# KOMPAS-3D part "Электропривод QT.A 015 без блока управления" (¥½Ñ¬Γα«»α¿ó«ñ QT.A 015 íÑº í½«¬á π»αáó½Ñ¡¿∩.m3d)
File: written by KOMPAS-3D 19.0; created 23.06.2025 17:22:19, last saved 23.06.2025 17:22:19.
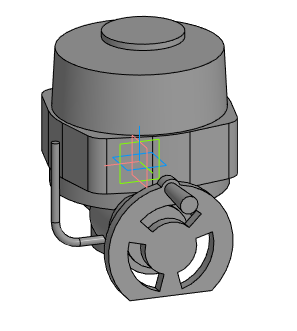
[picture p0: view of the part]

Document properties: Автор: Евгений; Полное имя файла: E:\Dendor Работа Сачек\3D для проектировщиков\3.5 Тип QT.А Электропривод\stp_Электропривод QT.A без блока управления\Электропривод QT.A 015 без блока управления.m3d

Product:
- Part/product: Электропривод QT.A 015 без блока управления

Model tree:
1. Операция без истории:1  (labels: Электропривод QT.A 015 без блока управления)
